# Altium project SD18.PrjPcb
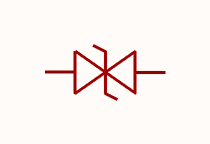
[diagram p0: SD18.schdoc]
1 sheet, 1 parts. Net scope: global (net labels, ports and power ports of the same name join across sheets).

## Sheet SD18.schdoc
size 127 x 101 mm

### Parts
D?  sd18  [SOD-323_L1.7-W1.3-LS2.5-BI]  (value not drawn)

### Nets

Not connected (* = marked no-connect by the designer): D? 1 2

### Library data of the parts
D? = sd18: 极性:双向;反向截止电压(Vrwm):18V;钳位电压:29V;峰值脉冲功率(Ppp):350W@8/20us;击穿电压(VBR):20V;; Manufacturer: JSMSEMI(杰盛微); AddInBom: yes; ModelId: 3c4d3117213c44d8be2b8463c3660d20; ModelTransform: 98.425,51.181,0,0,0,0,-0.001,0.006,0; Polarity: 双向; Reverse Stand-Off Voltage (Vrwm): 18V; Clamping Voltage: 29V; Voltage - Breakdown: 20V; Reverse Leakage Current (Ir): 1uA; Number of Channels: 单路; level of protection: IEC 61000-4-4；IEC 61000-4-2; Type: TVS; Junction Capacitance: 57pF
